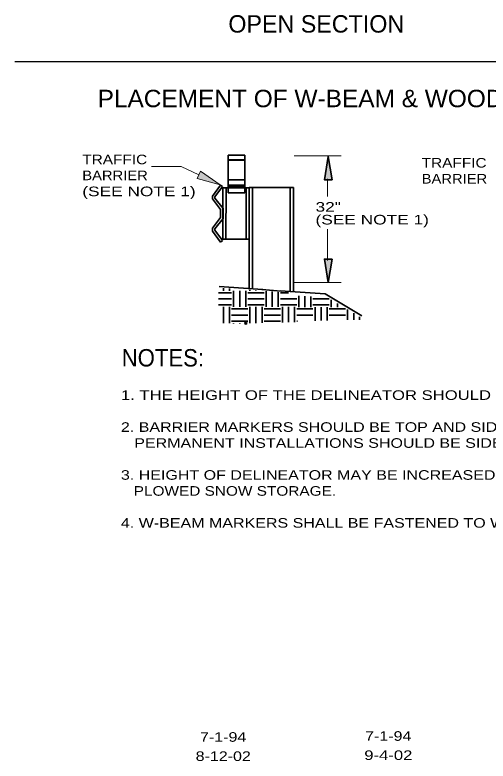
# Model space of a CAD drawing. Extents: x 2147527.1 to 2147534.3, y 2147768.5 to 2147778.6.
# Drawn here: x 2147527.127 to 2147530.091, y 2147768.724 to 2147773.395 of the extents above; entities that cross this region are included whole.
import ezdxf
from ezdxf.enums import TextEntityAlignment as Align

# ---------------------------------------------------------------- set-up
doc = ezdxf.new("R2010")
doc.units = 0
doc.header["$LTSCALE"] = 0.024
doc.header["$PDMODE"] = 32
doc.header["$PDSIZE"] = 0.012
for name, color, linetype, lineweight in [('1', 7, 'Continuous', 35), ('10', 7, 'Continuous', 13), ('63', 7, 'Continuous', 35)]:
    doc.layers.add(name, color=color, linetype=linetype, lineweight=lineweight)
doc.layers.add('12', color=7, linetype='Continuous')
doc.layers.add('13', color=7, linetype='Continuous')

msp = doc.modelspace()

# ---------------------------------------------------------------- hatches: boundary and pattern name
at = {"layer": '10'}
for points in [[(2147529.114, 2147772.363), (2147529.066, 2147772.363), (2147529.09, 2147772.509)], [(2147528.269, 2147772.371), (2147528.29, 2147772.416), (2147528.412, 2147772.331)], [(2147529.114, 2147771.866), (2147529.066, 2147771.866), (2147529.09, 2147771.72)]]:
    msp.add_hatch(color=256, dxfattribs=at).paths.add_polyline_path(points)

# ---------------------------------------------------------------- linework, layer by layer
at = {"layer": '1'}
for p, q in [((2147528.462, 2147772.517), (2147528.567, 2147772.517)), ((2147528.462, 2147772.281), (2147528.462, 2147772.517)), ((2147528.462, 2147772.487), (2147528.567, 2147772.487)), ((2147528.462, 2147772.486), (2147528.462, 2147772.363)), ((2147528.567, 2147772.486), (2147528.462, 2147772.486)), ((2147528.567, 2147772.517), (2147528.567, 2147772.281)), ((2147528.567, 2147772.363), (2147528.567, 2147772.486)), ((2147528.462, 2147772.363), (2147528.567, 2147772.363)), ((2147528.462, 2147772.362), (2147528.567, 2147772.362)), ((2147528.414, 2147772.33), (2147528.428, 2147772.32)), ((2147528.43, 2147772.315), (2147528.429, 2147771.992)), ((2147528.595, 2147772.312), (2147528.43, 2147772.312)), ((2147528.45, 2147772.315), (2147528.449, 2147771.992)), ((2147528.462, 2147772.329), (2147528.567, 2147772.329)), ((2147528.462, 2147772.324), (2147528.567, 2147772.324)), ((2147528.462, 2147772.318), (2147528.567, 2147772.318)), ((2147528.575, 2147772.314), (2147528.575, 2147771.991)), ((2147528.595, 2147772.314), (2147528.595, 2147771.682)), ((2147528.595, 2147772.314), (2147528.651, 2147772.314)), ((2147528.595, 2147772.314), (2147528.595, 2147771.991)), ((2147528.616, 2147772.314), (2147528.616, 2147771.68)), ((2147528.616, 2147772.314), (2147528.872, 2147772.314)), ((2147528.852, 2147772.314), (2147528.852, 2147771.664)), ((2147528.872, 2147772.314), (2147528.872, 2147771.662)), ((2147528.567, 2147772.281), (2147528.462, 2147772.281)), ((2147528.364, 2147772.06), (2147528.414, 2147772.126)), ((2147528.38, 2147772.055), (2147528.431, 2147772.12)), ((2147528.414, 2147772.126), (2147528.414, 2147772.152)), ((2147528.431, 2147772.12), (2147528.431, 2147772.152)), ((2147528.364, 2147772.042), (2147528.364, 2147772.06)), ((2147528.414, 2147771.973), (2147528.364, 2147772.042)), ((2147528.38, 2147772.048), (2147528.38, 2147772.055)), ((2147528.428, 2147771.983), (2147528.38, 2147772.048)), ((2147528.428, 2147771.983), (2147528.414, 2147771.973)), ((2147528.595, 2147771.991), (2147528.429, 2147771.992)), ((2147528.407, 2147771.695), (2147528.68, 2147771.676)), ((2147528.402, 2147771.656), (2147528.484, 2147771.656)), ((2147528.433, 2147771.668), (2147528.433, 2147771.684)), ((2147528.471, 2147771.668), (2147528.471, 2147771.682)), ((2147528.497, 2147771.567), (2147528.497, 2147771.668)), ((2147528.535, 2147771.567), (2147528.535, 2147771.668)), ((2147528.573, 2147771.567), (2147528.573, 2147771.668)), ((2147528.586, 2147771.656), (2147528.688, 2147771.656)), ((2147528.599, 2147771.668), (2147528.599, 2147771.673)), ((2147528.637, 2147771.668), (2147528.637, 2147771.67)), ((2147528.673, 2147771.675), (2147528.794, 2147771.666)), ((2147528.701, 2147771.567), (2147528.701, 2147771.666)), ((2147528.739, 2147771.567), (2147528.739, 2147771.663)), ((2147528.777, 2147771.567), (2147528.777, 2147771.66)), ((2147528.79, 2147771.656), (2147528.84, 2147771.656)), ((2147528.402, 2147771.618), (2147528.484, 2147771.618)), ((2147528.586, 2147771.618), (2147528.688, 2147771.618)), ((2147528.79, 2147771.618), (2147528.892, 2147771.618)), ((2147528.803, 2147771.618), (2147528.892, 2147771.618)), ((2147528.905, 2147771.566), (2147528.905, 2147771.637)), ((2147528.943, 2147771.566), (2147528.943, 2147771.635)), ((2147528.981, 2147771.566), (2147528.981, 2147771.632)), ((2147528.994, 2147771.618), (2147529.096, 2147771.618)), ((2147529.109, 2147771.566), (2147529.109, 2147771.611)), ((2147528.402, 2147771.58), (2147528.484, 2147771.58)), ((2147528.433, 2147771.465), (2147528.433, 2147771.567)), ((2147528.471, 2147771.465), (2147528.471, 2147771.567)), ((2147528.484, 2147771.554), (2147528.586, 2147771.554)), ((2147528.586, 2147771.58), (2147528.688, 2147771.58)), ((2147528.599, 2147771.465), (2147528.599, 2147771.567)), ((2147528.637, 2147771.466), (2147528.637, 2147771.567)), ((2147528.675, 2147771.467), (2147528.675, 2147771.567)), ((2147528.688, 2147771.554), (2147528.79, 2147771.554)), ((2147528.79, 2147771.58), (2147528.892, 2147771.58)), ((2147528.803, 2147771.579), (2147528.892, 2147771.579)), ((2147528.803, 2147771.47), (2147528.803, 2147771.567)), ((2147528.841, 2147771.471), (2147528.841, 2147771.567)), ((2147528.841, 2147771.476), (2147528.841, 2147771.566)), ((2147528.879, 2147771.472), (2147528.879, 2147771.567)), ((2147528.879, 2147771.477), (2147528.879, 2147771.566)), ((2147528.892, 2147771.554), (2147528.994, 2147771.554)), ((2147528.892, 2147771.554), (2147528.898, 2147771.554)), ((2147528.994, 2147771.579), (2147529.096, 2147771.579)), ((2147529.007, 2147771.48), (2147529.007, 2147771.566)), ((2147529.045, 2147771.481), (2147529.045, 2147771.566)), ((2147529.083, 2147771.482), (2147529.083, 2147771.566)), ((2147529.096, 2147771.554), (2147529.198, 2147771.554)), ((2147529.147, 2147771.566), (2147529.147, 2147771.588)), ((2147529.211, 2147771.486), (2147529.211, 2147771.55)), ((2147528.484, 2147771.516), (2147528.586, 2147771.516)), ((2147528.688, 2147771.516), (2147528.79, 2147771.516)), ((2147528.892, 2147771.516), (2147528.994, 2147771.516)), ((2147528.892, 2147771.516), (2147528.898, 2147771.516)), ((2147529.096, 2147771.516), (2147529.198, 2147771.516)), ((2147529.249, 2147771.486), (2147529.249, 2147771.527)), ((2147529.286, 2147771.487), (2147529.286, 2147771.504)), ((2147528.484, 2147771.478), (2147528.586, 2147771.478)), ((2147528.497, 2147771.463), (2147528.497, 2147771.465)), ((2147528.535, 2147771.464), (2147528.535, 2147771.465)), ((2147528.688, 2147771.478), (2147528.79, 2147771.478)), ((2147528.892, 2147771.478), (2147528.898, 2147771.478)), ((2147528.892, 2147771.477), (2147528.894, 2147771.477))]:
    msp.add_line(p, q, dxfattribs=at)
for points in [[(2147528.414, 2147772.33), (2147528.364, 2147772.261), (2147528.364, 2147772.243), (2147528.414, 2147772.177), (2147528.414, 2147772.152)], [(2147528.428, 2147772.32), (2147528.38, 2147772.255), (2147528.38, 2147772.248), (2147528.431, 2147772.183), (2147528.431, 2147772.152)], [(2147528.788, 2147771.668), (2147529.071, 2147771.649), (2147529.3, 2147771.512)]]:
    msp.add_lwpolyline(points, dxfattribs=at)
msp.add_point((2147528.573, 2147771.465), dxfattribs=at)
at = {"layer": '10'}
for p, q in [((2147528.877, 2147772.513), (2147529.17, 2147772.513)), ((2147528.169, 2147772.446), (2147527.982, 2147772.446)), ((2147528.28, 2147772.394), (2147528.169, 2147772.446)), ((2147529.086, 2147772.369), (2147529.086, 2147772.258)), ((2147529.086, 2147772.053), (2147529.086, 2147771.857)), ((2147528.877, 2147771.72), (2147529.17, 2147771.72))]:
    msp.add_line(p, q, dxfattribs=at)
at = {"layer": '10', "lineweight": 35}
for points in [[(2147529.114, 2147772.363), (2147529.066, 2147772.363), (2147529.09, 2147772.509)], [(2147529.114, 2147771.866), (2147529.066, 2147771.866), (2147529.09, 2147771.72)]]:
    msp.add_lwpolyline(points, close=True, dxfattribs=at)
at = {"layer": '10'}
msp.add_lwpolyline([(2147528.269, 2147772.371), (2147528.29, 2147772.416), (2147528.412, 2147772.331)], close=True, dxfattribs=at)
at = {"layer": '63', "lineweight": 25}
msp.add_line((2147527.127, 2147773.104), (2147534.243, 2147773.104), dxfattribs=at)

# ---------------------------------------------------------------- texts
at = {"layer": '1'}
for s, width, p in [('7-1-94', 1.25, (2147528.4315, 2147768.845)), ('7-1-94', 1.25, (2147529.4655, 2147768.851)), ('8-12-02', 1.25, (2147528.432, 2147768.725)), ('9-4-02', 1.3, (2147529.466, 2147768.731))]:
    msp.add_text(s, height=0.06, dxfattribs=dict(at, width=width)).set_placement(p, align=Align.CENTER)
at = {"layer": '12'}
msp.add_text('OPEN SECTION', height=0.109, dxfattribs=at).set_placement((2147528.464, 2147773.284))
for s, width, p in [('PLACEMENT OF W-BEAM & WOOD POST DELINEATORS', 1.05, (2147527.645, 2147772.817)), ('NOTES:', 0.95, (2147527.796, 2147771.194))]:
    msp.add_text(s, height=0.109, dxfattribs=dict(at, width=width)).set_placement(p)
at = {"layer": '13'}
for s, width, p in [('TRAFFIC', 1.2, (2147527.549, 2147772.46)), ('TRAFFIC', 1.2, (2147529.675, 2147772.439)), ('BARRIER', 1.15, (2147527.549, 2147772.36)), ('BARRIER', 1.15, (2147529.675, 2147772.339)), ('(SEE NOTE 1)', 1.35, (2147527.549, 2147772.26)), ('32"', 1.35, (2147529.01, 2147772.163)), ('(SEE NOTE 1)', 1.35, (2147529.01, 2147772.083)), ('1. THE HEIGHT OF THE DELINEATOR SHOULD BE WITHIN 2 INCHES OF THE DIMENSIONS SHOWN.', 1.3, (2147527.791, 2147770.985)), ('2. BARRIER MARKERS SHOULD BE TOP AND SIDE MOUNTED IN CONSTRUCTION ZONES.', 1.25, (2147527.791, 2147770.785)), ('   PERMANENT INSTALLATIONS SHOULD BE SIDE MOUNTED ONLY.', 1.25, (2147527.791, 2147770.685)), ('3. HEIGHT OF DELINEATOR MAY BE INCREASED AS NECESSARY IN AREAS HAVING EXCESSIVE', 1.25, (2147527.791, 2147770.485)), ('   PLOWED SNOW STORAGE.', 1.2, (2147527.791, 2147770.385)), ('4. W-BEAM MARKERS SHALL BE FASTENED TO WOOD OFFSET BLOCKS BY GALVANIZED 6 PENNY NAILS.', 1.25, (2147527.791, 2147770.185))]:
    msp.add_text(s, height=0.06, dxfattribs=dict(at, width=width)).set_placement(p)

doc.saveas('drawing.dxf')
